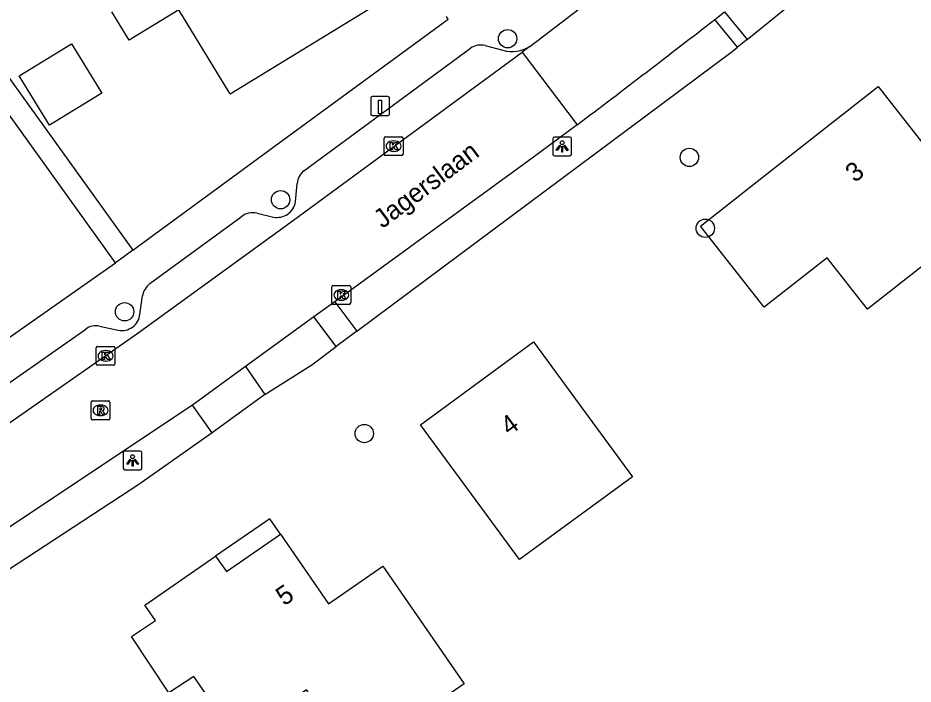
# Model space of a CAD drawing. Extents: x 162675 to 163482, y 379761 to 381227.
# Drawn here: x 163192.79 to 163240.45, y 381014.16 to 381049.64 of the extents above; entities that cross this region are included whole.
import ezdxf

# ---------------------------------------------------------------- set-up
doc = ezdxf.new("R2010")
doc.units = 0
for name, color, linetype in [('IMGEO_Berm_halfverhard', 7, 'Continuous'), ('IMGEO_Boom', 7, 'Continuous'), ('IMGEO_Kolk', 7, 'Continuous'), ('IMGEO_Laadpaal', 7, 'Continuous'), ('IMGEO_Lichtpunt', 7, 'Continuous'), ('IMGEO_Openbare_ruimte_label', 7, 'Continuous'), ('IMGEO_Pand', 7, 'Continuous'), ('IMGEO_Pand_nummerreeks', 7, 'Continuous'), ('IMGEO_Pand_overbouw', 7, 'Continuous'), ('IMGEO_Parkeervlak_halfverhard', 7, 'Continuous'), ('IMGEO_Rijbaan_lokaal_open', 7, 'Continuous'), ('IMGEO_Rioolput', 7, 'Continuous'), ('IMGEO_Voetpad_open', 7, 'Continuous')]:
    doc.layers.add(name, color=color, linetype=linetype)

msp = doc.modelspace()

# ---------------------------------------------------------------- linework, layer by layer
at = {"layer": 'IMGEO_Berm_halfverhard'}
msp.add_lwpolyline([(163203.137, 381027.533), (163199.236, 381024.792), (163186.779, 381016.648)], dxfattribs=at)
at = {"layer": 'IMGEO_Boom'}
for centre in [(163218.865, 381048.536), (163228.536, 381042.213), (163206.779, 381039.958), (163229.386, 381038.438), (163198.473, 381033.988), (163211.232, 381027.504)]:
    msp.add_circle(centre, 0.489, dxfattribs=at)
at = {"layer": 'IMGEO_Kolk'}
for p, q in [((163212.293, 381042.386), (163212.293, 381043.238)), ((163212.368, 381043.312), (163213.22, 381043.312)), ((163213.294, 381043.238), (163213.294, 381042.386)), ((163212.781, 381043.092), (163212.806, 381043.092)), ((163213.22, 381042.312), (163212.368, 381042.312)), ((163212.804, 381042.532), (163212.779, 381042.532)), ((163209.509, 381034.457), (163209.509, 381035.309)), ((163209.584, 381035.383), (163210.436, 381035.383)), ((163209.997, 381035.163), (163210.022, 381035.163)), ((163210.51, 381035.309), (163210.51, 381034.457)), ((163210.436, 381034.383), (163209.584, 381034.383)), ((163210.02, 381034.603), (163209.995, 381034.603)), ((163196.96, 381031.22), (163196.96, 381032.072)), ((163197.035, 381032.146), (163197.887, 381032.146)), ((163197.448, 381031.926), (163197.473, 381031.926)), ((163197.961, 381032.072), (163197.961, 381031.22)), ((163197.471, 381031.366), (163197.446, 381031.366)), ((163197.887, 381031.146), (163197.035, 381031.146))]:
    msp.add_line(p, q, dxfattribs=at)
for points in [[(163212.293, 381042.386), (163212.293, 381043.238)], [(163212.368, 381043.312), (163213.22, 381043.312)], [(163213.294, 381043.238), (163213.294, 381042.386)], [(163212.614, 381043.012), (163212.737, 381043.012), (163212.737, 381042.861), (163212.867, 381043.012), (163213.031, 381043.012), (163212.885, 381042.861), (163213.038, 381042.612), (163212.886, 381042.612), (163212.801, 381042.776), (163212.737, 381042.709), (163212.737, 381042.612), (163212.614, 381042.612), (163212.614, 381043.012)], [(163213.22, 381042.312), (163212.368, 381042.312)], [(163209.509, 381034.457), (163209.509, 381035.309)], [(163209.584, 381035.383), (163210.436, 381035.383)], [(163210.51, 381035.309), (163210.51, 381034.457)], [(163209.83, 381035.083), (163209.953, 381035.083), (163209.953, 381034.932), (163210.083, 381035.083), (163210.247, 381035.083), (163210.101, 381034.932), (163210.254, 381034.683), (163210.102, 381034.683), (163210.017, 381034.847), (163209.953, 381034.78), (163209.953, 381034.683), (163209.83, 381034.683), (163209.83, 381035.083)], [(163210.436, 381034.383), (163209.584, 381034.383)], [(163196.96, 381031.22), (163196.96, 381032.072)], [(163197.035, 381032.146), (163197.887, 381032.146)], [(163197.281, 381031.846), (163197.404, 381031.846), (163197.404, 381031.695), (163197.534, 381031.846), (163197.698, 381031.846), (163197.552, 381031.695), (163197.705, 381031.446), (163197.553, 381031.446), (163197.468, 381031.61), (163197.404, 381031.543), (163197.404, 381031.446), (163197.281, 381031.446), (163197.281, 381031.846)], [(163197.961, 381032.072), (163197.961, 381031.22)], [(163197.887, 381031.146), (163197.035, 381031.146)]]:
    msp.add_lwpolyline(points, dxfattribs=at)
for centre, start, end in [((163212.37, 381043.236), 91.552, 178.448), ((163212.37, 381043.236), 91.552, 178.448), ((163213.218, 381043.236), 1.552, 88.448), ((163213.218, 381043.236), 1.552, 88.448), ((163212.37, 381042.388), 181.552, 268.448), ((163212.37, 381042.388), 181.552, 268.448), ((163213.218, 381042.388), 271.552, 358.448), ((163213.218, 381042.388), 271.552, 358.448), ((163209.586, 381035.307), 91.552, 178.448), ((163209.586, 381035.307), 91.552, 178.448), ((163210.434, 381035.307), 1.552, 88.448), ((163210.434, 381035.307), 1.552, 88.448), ((163209.586, 381034.459), 181.552, 268.448), ((163209.586, 381034.459), 181.552, 268.448), ((163210.434, 381034.459), 271.552, 358.448), ((163210.434, 381034.459), 271.552, 358.448), ((163197.037, 381032.07), 91.552, 178.448), ((163197.037, 381032.07), 91.552, 178.448), ((163197.885, 381032.07), 1.552, 88.448), ((163197.885, 381032.07), 1.552, 88.448), ((163197.037, 381031.222), 181.552, 268.448), ((163197.037, 381031.222), 181.552, 268.448), ((163197.885, 381031.222), 271.552, 358.448), ((163197.885, 381031.222), 271.552, 358.448)]:
    msp.add_arc(centre, 0.0765, start, end, dxfattribs=at)
for centre, major_axis, ratio, start_param, end_param in [((163212.78, 381042.812), (-0.387, 0.002), 0.722429, 4.712389, 7.853982), ((163212.805, 381042.812), (-0.39, 0.002), 0.717154, 1.570796, 4.712389), ((163209.996, 381034.883), (-0.387, 0.002), 0.722429, 4.712389, 7.853982), ((163210.021, 381034.883), (-0.39, 0.002), 0.717154, 1.570796, 4.712389), ((163197.447, 381031.646), (-0.387, 0.002), 0.722429, 4.712389, 7.853982), ((163197.472, 381031.646), (-0.39, 0.002), 0.717154, 1.570796, 4.712389)]:
    msp.add_ellipse(centre, major_axis=major_axis, ratio=ratio, start_param=start_param, end_param=end_param, dxfattribs=at)
at = {"layer": 'IMGEO_Laadpaal'}
for p, q in [((163211.577, 381045.365), (163211.577, 381044.524)), ((163211.577, 381045.365), (163211.577, 381044.524)), ((163212.493, 381045.449), (163211.652, 381045.449)), ((163212.493, 381045.449), (163211.652, 381045.449)), ((163212.577, 381044.533), (163212.577, 381045.374)), ((163212.577, 381044.533), (163212.577, 381045.374)), ((163211.661, 381044.449), (163212.502, 381044.449)), ((163211.661, 381044.449), (163212.502, 381044.449))]:
    msp.add_line(p, q, dxfattribs=at)
msp.add_lwpolyline([(163211.992, 381045.262), (163212.152, 381045.262), (163212.152, 381044.529), (163211.992, 381044.529), (163211.992, 381045.262)], dxfattribs=at)
for centre, start, end in [((163211.655, 381045.371), 92.4484, 184.2845), ((163211.655, 381045.371), 92.4484, 184.2845), ((163212.499, 381045.371), 2.4484, 94.2845), ((163212.499, 381045.371), 2.4484, 94.2845), ((163211.655, 381044.527), 182.4484, 274.2845), ((163211.655, 381044.527), 182.4484, 274.2845), ((163212.499, 381044.527), 272.4484, 4.2845), ((163212.499, 381044.527), 272.4484, 4.2845)]:
    msp.add_arc(centre, 0.0779, start, end, dxfattribs=at)
at = {"layer": 'IMGEO_Lichtpunt'}
for p, q in [((163222.17, 381043.292), (163221.362, 381043.292)), ((163222.17, 381043.292), (163221.362, 381043.292)), ((163221.268, 381043.197), (163221.268, 381042.39)), ((163221.268, 381043.197), (163221.268, 381042.39)), ((163222.264, 381042.39), (163222.264, 381043.197)), ((163222.264, 381042.39), (163222.264, 381043.197)), ((163221.362, 381042.296), (163222.17, 381042.296)), ((163221.362, 381042.296), (163222.17, 381042.296)), ((163199.301, 381026.569), (163198.493, 381026.569)), ((163199.301, 381026.569), (163198.493, 381026.569)), ((163198.399, 381026.474), (163198.399, 381025.667)), ((163198.399, 381026.474), (163198.399, 381025.667)), ((163199.395, 381025.667), (163199.395, 381026.474)), ((163199.395, 381025.667), (163199.395, 381026.474)), ((163198.493, 381025.573), (163199.301, 381025.573)), ((163198.493, 381025.573), (163199.301, 381025.573))]:
    msp.add_line(p, q, dxfattribs=at)
for points in [[(163221.642, 381042.861), (163221.681, 381042.833), (163221.493, 381042.571), (163221.455, 381042.598), (163221.642, 381042.861)], [(163221.744, 381042.813), (163221.791, 381042.813), (163221.791, 381042.491), (163221.744, 381042.491), (163221.744, 381042.813)], [(163221.854, 381042.833), (163221.892, 381042.86), (163222.079, 381042.598), (163222.04, 381042.57), (163221.854, 381042.833)], [(163198.773, 381026.138), (163198.812, 381026.11), (163198.624, 381025.848), (163198.586, 381025.875), (163198.773, 381026.138)], [(163198.875, 381026.09), (163198.922, 381026.09), (163198.922, 381025.768), (163198.875, 381025.768), (163198.875, 381026.09)], [(163198.985, 381026.11), (163199.023, 381026.137), (163199.21, 381025.875), (163199.171, 381025.847), (163198.985, 381026.11)]]:
    msp.add_lwpolyline(points, dxfattribs=at)
for centre in [(163221.767, 381042.995), (163198.898, 381026.272)]:
    msp.add_circle(centre, 0.0994, dxfattribs=at)
for centre, start, end in [((163221.362, 381043.197), 90, 180), ((163221.362, 381043.197), 90, 180), ((163222.17, 381043.197), 0, 90), ((163222.17, 381043.197), 0, 90), ((163221.362, 381042.39), 180, 270), ((163221.362, 381042.39), 180, 270), ((163222.17, 381042.39), 270, 0), ((163222.17, 381042.39), 270, 360), ((163198.493, 381026.474), 90, 180), ((163198.493, 381026.474), 90, 180), ((163199.301, 381026.474), 0, 90), ((163199.301, 381026.474), 0, 90), ((163198.493, 381025.667), 180, 270), ((163198.493, 381025.667), 180, 270), ((163199.301, 381025.667), 270, 0), ((163199.301, 381025.667), 270, 360)]:
    msp.add_arc(centre, 0.0946, start, end, dxfattribs=at)
at = {"layer": 'IMGEO_Pand'}
for points in [[(163208.108, 381056.275), (163211.764, 381050.276), (163204.093, 381045.589), (163204.028, 381045.697), (163201.364, 381050.069), (163198.71, 381048.452), (163197.786, 381049.969)], [(163195.655, 381048.256), (163197.256, 381045.628), (163194.47, 381043.931), (163192.869, 381046.56), (163195.655, 381048.256)], [(163235.87, 381036.87), (163232.512, 381034.234), (163229.122, 381038.553), (163232.48, 381041.189), (163238.586, 381045.982), (163241.673, 381042.049), (163244.132, 381038.917), (163238.026, 381034.124), (163235.87, 381036.87)], [(163219.489, 381020.791), (163217.183, 381023.937), (163214.228, 381027.97), (163220.246, 381032.38), (163223.201, 381028.347), (163225.507, 381025.201), (163219.489, 381020.791)], [(163216.549, 381014.172), (163210.72, 381010.136), (163208.153, 381013.844), (163204.436, 381011.271), (163202.152, 381014.57), (163200.83, 381013.694), (163198.84, 381016.694), (163200.116, 381017.54), (163199.546, 381018.361), (163203.321, 381020.977), (163203.891, 381020.155), (163206.772, 381022.138), (163209.333, 381018.435), (163212.214, 381020.433), (163216.549, 381014.172)]]:
    msp.add_lwpolyline(points, dxfattribs=at)
at = {"layer": 'IMGEO_Pand_overbouw'}
msp.add_lwpolyline([(163203.321, 381020.977), (163203.891, 381020.155), (163206.772, 381022.138), (163206.206, 381022.96)], close=True, dxfattribs=at)
at = {"layer": 'IMGEO_Parkeervlak_halfverhard'}
for points in [[(163231.612, 381048.494), (163241.963, 381056.895)], [(163210.838, 381032.957), (163230.812, 381047.845), (163231.099, 381048.078)], [(163205.931, 381029.575), (163208.437, 381031.168), (163209.732, 381032.133)]]:
    msp.add_lwpolyline(points, dxfattribs=at)
at = {"layer": 'IMGEO_Rijbaan_lokaal_open'}
for points in [[(163220.037, 381048.125), (163224.616, 381051.636), (163227.381, 381053.767)], [(163229.893, 381049.563), (163230.414, 381049.97)], [(163220.037, 381048.125), (163219.63, 381047.825)], [(163190.753, 381026.973), (163199.121, 381032.82), (163207.473, 381038.875), (163219.63, 381047.825)], [(163219.63, 381047.825), (163222.56, 381043.953)], [(163222.56, 381043.953), (163220.171, 381042.171), (163209.668, 381034.526)], [(163209.668, 381034.526), (163208.553, 381033.715)], [(163208.553, 381033.715), (163204.914, 381031.066)], [(163204.914, 381031.066), (163202.085, 381029.006)], [(163202.085, 381029.006), (163180.449, 381014.591), (163173.897, 381011.259)]]:
    msp.add_lwpolyline(points, dxfattribs=at)
msp.add_arc((162913.054, 381456.115), 515.433, 306.90408, 307.93041, dxfattribs=at)
at = {"layer": 'IMGEO_Rioolput'}
for p, q in [((163196.692, 381028.311), (163196.692, 381029.163)), ((163196.767, 381029.237), (163197.619, 381029.237)), ((163197.18, 381029.017), (163197.205, 381029.017)), ((163197.693, 381029.163), (163197.693, 381028.311)), ((163197.203, 381028.457), (163197.178, 381028.457)), ((163197.619, 381028.237), (163196.767, 381028.237))]:
    msp.add_line(p, q, dxfattribs=at)
for points in [[(163196.692, 381028.311), (163196.692, 381029.163)], [(163196.767, 381029.237), (163197.619, 381029.237)], [(163197.281, 381028.935), (163197.029, 381028.937), (163197.029, 381028.537)], [(163197.693, 381029.163), (163197.693, 381028.311)], [(163197.029, 381028.537), (163197.153, 381028.537), (163197.153, 381028.699), (163197.164, 381028.699)], [(163197.207, 381028.856), (163197.153, 381028.856), (163197.153, 381028.775)], [(163197.153, 381028.775), (163197.205, 381028.775)], [(163197.211, 381028.67), (163197.282, 381028.537), (163197.422, 381028.537), (163197.357, 381028.663)], [(163197.619, 381028.237), (163196.767, 381028.237)]]:
    msp.add_lwpolyline(points, dxfattribs=at)
for centre, radius, start, end in [((163196.769, 381029.161), 0.0765, 91.552, 178.448), ((163196.769, 381029.161), 0.0765, 91.552, 178.448), ((163197.28, 381028.825), 0.109, 350.3612, 89.416), ((163197.617, 381029.161), 0.0765, 1.552, 88.448), ((163197.617, 381029.161), 0.0765, 1.552, 88.448), ((163197.163, 381028.646), 0.0533, 26.0293, 88.6989), ((163197.189, 381028.964), 0.19, 274.7715, 282.9687), ((163197.213, 381028.76), 0.0964, 77.0061, 93.1865), ((163197.227, 381028.817), 0.0378, 276.6634, 79.6772), ((163197.278, 381028.825), 0.112, 277.5842, 350.9817), ((163197.262, 381028.61), 0.108, 29.5134, 73.7905), ((163196.769, 381028.313), 0.0765, 181.552, 268.448), ((163196.769, 381028.313), 0.0765, 181.552, 268.448), ((163197.617, 381028.313), 0.0765, 271.552, 358.448), ((163197.617, 381028.313), 0.0765, 271.552, 358.448)]:
    msp.add_arc(centre, radius, start, end, dxfattribs=at)
for centre, major_axis, ratio, start_param, end_param in [((163197.179, 381028.737), (-0.387, 0.002), 0.722429, 4.712389, 7.853982), ((163197.204, 381028.737), (-0.39, 0.002), 0.717154, 1.570796, 4.712389)]:
    msp.add_ellipse(centre, major_axis=major_axis, ratio=ratio, start_param=start_param, end_param=end_param, dxfattribs=at)
at = {"layer": 'IMGEO_Voetpad_open'}
for points in [[(163197.985, 381036.604), (163183.06, 381057.381), (163183.983, 381058.045), (163198.909, 381037.268)], [(163230.414, 381049.97), (163231.612, 381048.494)], [(163198.909, 381037.268), (163207.172, 381043.323), (163215.696, 381049.583), (163215.608, 381049.723)], [(163231.099, 381048.078), (163229.893, 381049.563)], [(163231.612, 381048.494), (163231.099, 381048.078)], [(163208.016, 381041.504), (163216.893, 381048.033)], [(163217.669, 381048.171), (163218.614, 381047.919)], [(163207.567, 381039.844), (163207.666, 381040.824)], [(163199.823, 381035.495), (163204.672, 381039.041)], [(163205.529, 381039.241), (163206.399, 381039.033)], [(163198.909, 381037.268), (163198.426, 381036.914), (163197.985, 381036.604)], [(163189.322, 381030.523), (163197.985, 381036.604)], [(163199.286, 381033.852), (163199.419, 381034.837)], [(163209.668, 381034.526), (163210.838, 381032.957)], [(163209.732, 381032.133), (163208.553, 381033.715)], [(163197.14, 381033.22), (163198.134, 381033.012)], [(163191.473, 381029.623), (163196.402, 381033.069)], [(163210.838, 381032.957), (163209.732, 381032.133)], [(163204.914, 381031.066), (163205.931, 381029.575)], [(163205.931, 381029.575), (163203.137, 381027.533)], [(163203.137, 381027.533), (163202.085, 381029.006)]]:
    msp.add_lwpolyline(points, dxfattribs=at)
for centre, radius, start, end in [((163217.439, 381047.212), 0.986, 76.5197, 123.6478), ((163219.097, 381049.599), 1.748, 253.9575, 302.5168), ((163208.642, 381040.752), 0.978, 129.7572, 175.7725), ((163206.591, 381040.004), 0.989, 258.828, 350.7203), ((163205.305, 381038.264), 1.002, 77.0953, 129.1769), ((163200.492, 381034.631), 1.092, 127.7556, 169.146), ((163198.338, 381033.943), 0.953, 257.6644, 354.5322), ((163196.943, 381032.305), 0.936, 77.8326, 125.2944)]:
    msp.add_arc(centre, radius, start, end, dxfattribs=at)

# ---------------------------------------------------------------- texts
at = {"layer": 'IMGEO_Openbare_ruimte_label'}
msp.add_text('Jagerslaan', height=1, rotation=36.9501, dxfattribs=at).set_placement((163212.205, 381038.395))
at = {"layer": 'IMGEO_Pand_nummerreeks'}
for s, rotation, p in [('3', 38.1303, (163237.342, 381040.836)), ('4', 36.234, (163218.953, 381027.367)), ('5', 34.544, (163206.968, 381018.291))]:
    msp.add_text(s, height=1, rotation=rotation, dxfattribs=at).set_placement(p)

doc.saveas('drawing.dxf')
